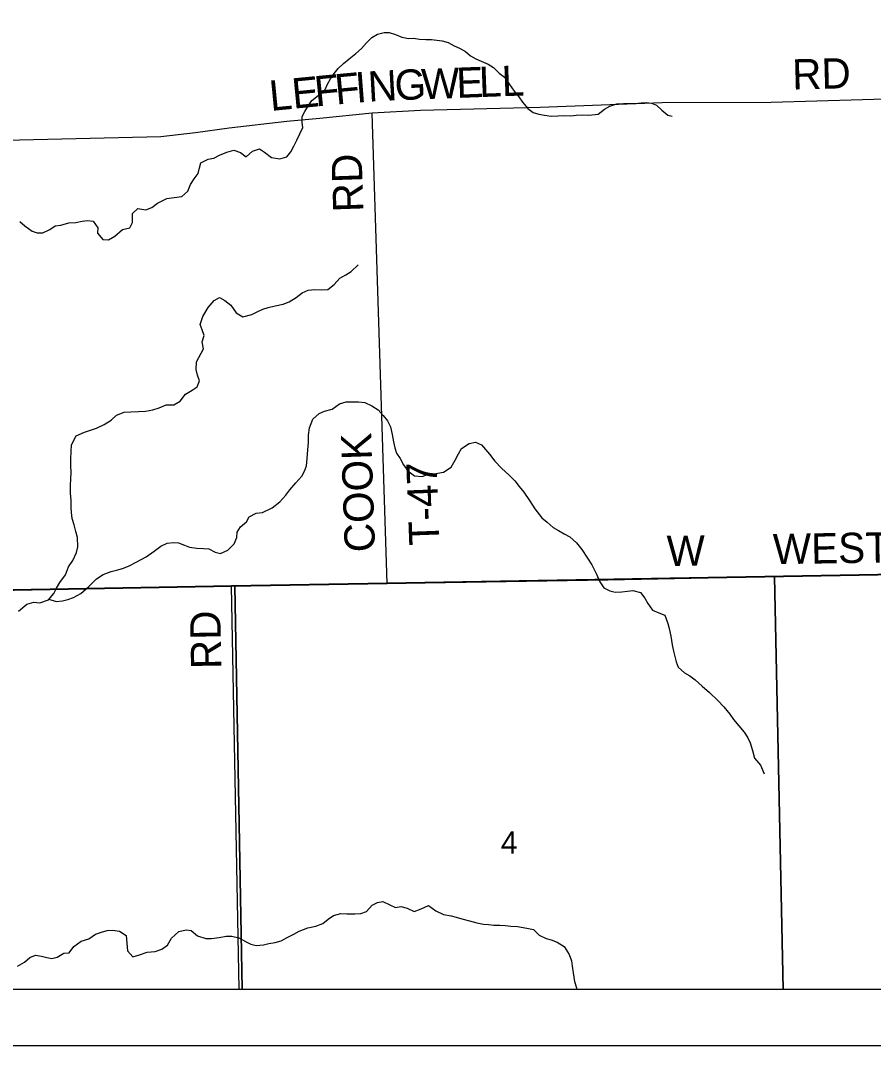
# Model space of a CAD drawing. Extents: x 0 to 34, y 0 to 22.
# Drawn here: x 4.883 to 6.483, y 9.902 to 11.824 of the extents above; entities that cross this region are included whole.
import ezdxf

# ---------------------------------------------------------------- set-up
doc = ezdxf.new("R2010")
doc.units = 0
for name, color, linetype in [('GM_X_Corporation', 7, 'Continuous'), ('GM_X_County_Road', 7, 'Continuous'), ('GM_X_County_Road_Text', 7, 'Continuous'), ('GM_X_Minor_River', 7, 'Continuous'), ('GM_X_Section_Text', 7, 'Continuous'), ('GM_X_Township_Road', 7, 'Continuous'), ('GM_X_Township_Road_Text', 7, 'Continuous'), ('SH_Data', 7, 'Continuous')]:
    doc.layers.add(name, color=color, linetype=linetype)

msp = doc.modelspace()

# ---------------------------------------------------------------- linework, layer by layer
at = {"layer": 'GM_X_Corporation'}
msp.add_lwpolyline([(6.7217, 15.9197), (5.5749, 15.8972), (5.1967, 15.8898), (4.4889, 15.8766), (2.7231, 15.8419), (2.7231, 10.7149), (3.2181, 10.7269), (4.6326, 10.7519), (5.2789, 10.7635), (5.571, 10.7686), (6.8097, 10.7901)], dxfattribs=at)
for points in [[(3.2288, 10.0075), (9.4322, 10.0075), (9.4266, 10.7304), (9.4256, 10.8527), (9.3392, 10.8506), (8.3328, 10.8251), (7.8767, 10.8135), (6.8339, 10.7907), (6.8097, 10.7901), (5.571, 10.7686), (5.2789, 10.7635), (4.6326, 10.7519), (3.2181, 10.7269)], [(6.3131, 10.0075), (7.3462, 10.0075), (7.3327, 10.8022), (6.8431, 10.7918), (6.4039, 10.7821), (6.297, 10.7801)], [(4.267, 10.0075), (5.299, 10.0075), (5.2854, 10.7626), (5.1477, 10.7602), (4.7405, 10.7544), (4.3079, 10.7484), (4.2548, 10.7474)], [(5.299, 10.0075), (6.3131, 10.0075), (6.297, 10.7801), (5.9849, 10.7744), (5.5658, 10.7674), (5.2854, 10.7626)]]:
    msp.add_lwpolyline(points, close=True, dxfattribs=at)
at = {"layer": 'GM_X_County_Road'}
msp.add_lwpolyline([(3.2183, 10.7263), (4.6328, 10.7513), (5.2791, 10.763), (5.5712, 10.7681), (6.8099, 10.7896)], dxfattribs=at)
at = {"layer": 'GM_X_Minor_River'}
for points in [[(5.4017, 11.5992), (5.4126, 11.6228), (5.4116, 11.6325), (5.4116, 11.6432), (5.4168, 11.6527), (5.4232, 11.6642), (5.4299, 11.6737), (5.4447, 11.6852), (5.4545, 11.6941), (5.4593, 11.704), (5.4649, 11.7143), (5.4713, 11.7239), (5.4788, 11.7334), (5.489, 11.743), (5.4996, 11.7518), (5.5121, 11.7618), (5.523, 11.771), (5.5321, 11.7818), (5.5419, 11.7917), (5.5528, 11.7979), (5.565, 11.801), (5.5745, 11.8007), (5.5863, 11.797), (5.5985, 11.7922), (5.6107, 11.79), (5.6202, 11.7905), (5.6313, 11.7887), (5.6434, 11.788), (5.6541, 11.7881), (5.6739, 11.7852), (5.6853, 11.7823), (5.6964, 11.7763), (5.7063, 11.7718), (5.7178, 11.7654), (5.7274, 11.7575), (5.7373, 11.7515), (5.7473, 11.7471), (5.7602, 11.7415), (5.7702, 11.7351), (5.7809, 11.7249), (5.7909, 11.7174), (5.8001, 11.7038), (5.809, 11.6913), (5.8175, 11.6804), (5.8248, 11.6705), (5.8344, 11.6584), (5.8447, 11.6509), (5.855, 11.648), (5.8657, 11.6458), (5.8786, 11.644), (5.8912, 11.6448), (5.9026, 11.6453), (5.9155, 11.645), (5.925, 11.6459), (5.9368, 11.6467), (5.949, 11.6461), (5.9665, 11.6477), (5.9785, 11.6573), (5.9884, 11.6627), (6.0013, 11.667), (6.0142, 11.6679), (6.0355, 11.6681), (6.0469, 11.6693), (6.0572, 11.6698), (6.0667, 11.6687), (6.0762, 11.665), (6.0862, 11.6556), (6.0973, 11.6458), (6.1053, 11.6443)], [(4.8916, 11.4386), (4.9051, 11.4286), (4.915, 11.4253), (4.9256, 11.4255), (4.9387, 11.4315), (4.9485, 11.4385), (4.959, 11.4395), (4.9741, 11.4439), (4.9874, 11.445), (4.9991, 11.4471), (5.0093, 11.4484), (5.0195, 11.4471), (5.0285, 11.4347), (5.0279, 11.4249), (5.0376, 11.4129), (5.0486, 11.4123), (5.0606, 11.419), (5.0748, 11.4318), (5.0883, 11.4348), (5.0935, 11.4447), (5.0932, 11.4614), (5.1032, 11.4711), (5.1184, 11.4688), (5.1297, 11.4728), (5.1405, 11.481), (5.1578, 11.49), (5.1718, 11.4914), (5.1862, 11.4932), (5.197, 11.5037), (5.202, 11.5163), (5.2091, 11.5264), (5.2164, 11.5368), (5.2189, 11.5471), (5.2218, 11.5566), (5.2356, 11.5633), (5.2458, 11.5651), (5.2567, 11.571), (5.2703, 11.5765), (5.2835, 11.5802), (5.2957, 11.5763), (5.3064, 11.5677), (5.3184, 11.5782), (5.3315, 11.583), (5.3411, 11.5764), (5.3538, 11.5664), (5.3698, 11.564), (5.383, 11.5677), (5.3904, 11.5773), (5.3959, 11.5881), (5.4017, 11.5992)], [(4.882, 11.4464), (4.8916, 11.4386)], [(5.0147, 11.0554), (5.026, 11.059), (5.0402, 11.0658), (5.0533, 11.0744), (5.0634, 11.0837), (5.0781, 11.0889), (5.0902, 11.0899), (5.1046, 11.0902), (5.1175, 11.0908), (5.1318, 11.0934), (5.1435, 11.097), (5.1566, 11.1026), (5.171, 11.1032), (5.1827, 11.1095), (5.193, 11.123), (5.205, 11.1305), (5.2147, 11.1367), (5.2191, 11.1478), (5.2155, 11.1584), (5.2126, 11.169), (5.2135, 11.1838), (5.2267, 11.208), (5.2242, 11.2212), (5.2277, 11.2331), (5.2241, 11.2433), (5.2202, 11.2535), (5.2252, 11.2687), (5.2355, 11.2853), (5.2466, 11.2988), (5.2567, 11.3039), (5.2667, 11.2988), (5.2775, 11.2899), (5.2876, 11.2753), (5.3006, 11.2679), (5.3172, 11.272), (5.327, 11.2775), (5.3379, 11.2823), (5.3477, 11.2855), (5.3612, 11.2888), (5.376, 11.2914), (5.3872, 11.2962), (5.4003, 11.3044), (5.4116, 11.313), (5.4225, 11.3178), (5.4353, 11.3191), (5.4478, 11.3186), (5.4599, 11.3192), (5.4715, 11.3282), (5.4819, 11.3406), (5.4935, 11.3465), (5.5033, 11.3527), (5.5163, 11.3651)], [(4.9367, 10.7383), (4.9505, 10.7339), (4.9622, 10.7357), (4.9724, 10.7378), (4.9826, 10.7414), (4.9968, 10.7493), (5.0114, 10.7625), (5.0259, 10.7764), (5.0382, 10.7846), (5.0537, 10.7906), (5.0657, 10.7935), (5.0763, 10.7964), (5.0872, 10.8011), (5.1018, 10.8086), (5.1191, 10.8181), (5.1341, 10.8283), (5.1468, 10.8376), (5.1584, 10.8435), (5.1701, 10.8449), (5.1796, 10.844), (5.1907, 10.8396), (5.2006, 10.836), (5.2143, 10.834), (5.2264, 10.8338), (5.2367, 10.8329), (5.2485, 10.8267), (5.2584, 10.8242), (5.2723, 10.8302), (5.2839, 10.8425), (5.2889, 10.8544), (5.2895, 10.8643), (5.2958, 10.8743), (5.307, 10.8833), (5.3121, 10.8932), (5.3252, 10.8999), (5.337, 10.9013), (5.3554, 10.9096), (5.3699, 10.9209), (5.3811, 10.9333), (5.3885, 10.9437), (5.3996, 10.9568), (5.4107, 10.9692), (5.4162, 10.9788), (5.4198, 10.9888), (5.4211, 11.0025), (5.4219, 11.0188), (5.4236, 11.0325), (5.4237, 11.0458), (5.425, 11.0599), (5.4315, 11.076), (5.4434, 11.0864), (5.4536, 11.0908), (5.4679, 11.0949), (5.4813, 11.105), (5.4942, 11.1083), (5.5074, 11.1082), (5.5173, 11.1084), (5.529, 11.1075), (5.542, 11.1009), (5.5539, 11.0935), (5.5632, 11.0827), (5.5714, 11.073), (5.5773, 11.0617), (5.5806, 11.0473), (5.5831, 11.0337), (5.5856, 11.0223), (5.5884, 11.0121), (5.595, 11.0024), (5.6013, 10.9907), (5.6095, 10.9791), (5.6221, 10.9698), (5.6366, 10.9686), (5.6486, 10.973), (5.6592, 10.9736), (5.6766, 10.9766), (5.6908, 10.986), (5.6985, 10.9994), (5.7044, 11.0113), (5.7102, 11.0209), (5.7245, 11.0303), (5.7365, 11.0332), (5.748, 11.0277), (5.7627, 11.0105), (5.7728, 10.9974), (5.7852, 10.9844), (5.7995, 10.971), (5.8106, 10.9602), (5.8184, 10.95), (5.8269, 10.9392), (5.8378, 10.9238), (5.8476, 10.9081), (5.8608, 10.8912), (5.8708, 10.883), (5.8824, 10.873), (5.8923, 10.8671), (5.903, 10.8613), (5.9134, 10.8554), (5.9261, 10.8442), (5.9358, 10.8319), (5.9463, 10.8154), (5.9545, 10.8026)], [(4.8796, 10.7162), (4.8953, 10.7291), (4.9085, 10.7327), (4.9199, 10.7318), (4.9357, 10.7371), (4.9457, 10.749), (4.9512, 10.7594), (4.9574, 10.7698), (4.9678, 10.7844), (4.9732, 10.7989), (4.9817, 10.8109), (4.9882, 10.8258), (4.991, 10.8369), (4.9903, 10.854), (4.9875, 10.8653), (4.9838, 10.8778), (4.9802, 10.8899), (4.9792, 10.9009), (4.9787, 10.9103), (4.9784, 10.9236), (4.9771, 10.9373), (4.9772, 10.9521), (4.9781, 10.9635), (4.9786, 10.9768), (4.978, 10.9886), (4.9781, 11.0019), (4.9783, 11.0156), (4.9792, 11.0281), (4.9876, 11.045), (5.0034, 11.0514), (5.0147, 11.0554)], [(5.9545, 10.8026), (5.9632, 10.7853), (5.9699, 10.771), (5.9769, 10.7597), (5.9884, 10.7539), (5.9987, 10.7514), (6.0111, 10.752), (6.0213, 10.7537), (6.0316, 10.7547), (6.046, 10.7508), (6.0538, 10.7403), (6.0597, 10.7301), (6.0686, 10.7178), (6.0801, 10.7131), (6.0915, 10.7087), (6.0971, 10.6932), (6.0996, 10.6834), (6.1025, 10.669), (6.1054, 10.6531), (6.1075, 10.641), (6.1104, 10.6312), (6.1128, 10.621), (6.1164, 10.6108), (6.1284, 10.6004), (6.1387, 10.5945), (6.1487, 10.5875), (6.1614, 10.5756), (6.1753, 10.5633), (6.1907, 10.5488), (6.2019, 10.5368), (6.2135, 10.523), (6.2202, 10.5132), (6.2403, 10.4889), (6.2473, 10.4788), (6.2513, 10.469), (6.2557, 10.4547), (6.2598, 10.4407), (6.2706, 10.4272), (6.2778, 10.411)], [(5.1938, 10.1183), (5.2033, 10.117), (5.2156, 10.107), (5.2312, 10.1023), (5.2418, 10.1025), (5.2558, 10.1043), (5.2691, 10.1065), (5.2797, 10.1067), (5.2926, 10.1035), (5.3052, 10.0969), (5.3152, 10.0918), (5.3251, 10.0893), (5.3391, 10.0904), (5.3489, 10.0928), (5.361, 10.0946), (5.3723, 10.0982), (5.3835, 10.1041), (5.3959, 10.1101), (5.4057, 10.1163), (5.4222, 10.122), (5.4369, 10.1253), (5.4505, 10.1301), (5.4606, 10.1383), (5.4703, 10.1457), (5.4842, 10.1494), (5.4953, 10.1484), (5.51, 10.1483), (5.5218, 10.1489), (5.5323, 10.1526), (5.5427, 10.1645), (5.5528, 10.1697), (5.563, 10.1714), (5.576, 10.1652), (5.5867, 10.1604), (5.5965, 10.1622), (5.6083, 10.1593), (5.6217, 10.1531), (5.6349, 10.158), (5.6484, 10.1643), (5.6619, 10.1543), (5.6764, 10.147), (5.6908, 10.1446), (5.7004, 10.1425), (5.711, 10.1389), (5.7251, 10.1357), (5.7392, 10.1318), (5.7514, 10.1294), (5.7609, 10.1285), (5.7707, 10.1275), (5.7821, 10.127), (5.7931, 10.1264), (5.803, 10.1255), (5.8155, 10.1246), (5.833, 10.1219), (5.8452, 10.119), (5.856, 10.1086), (5.8689, 10.1024), (5.8785, 10.0999), (5.8895, 10.0952), (5.9026, 10.0875), (5.9119, 10.0721), (5.9163, 10.0604), (5.918, 10.0502), (5.9194, 10.038), (5.922, 10.0217), (5.9256, 10.0097), (5.9265, 10.0075)], [(4.8779, 10.0503), (4.8907, 10.0578), (4.9007, 10.0667), (4.9116, 10.0711), (4.9227, 10.0694), (4.9326, 10.0666), (4.9424, 10.0645), (4.9523, 10.067), (4.9646, 10.0748), (4.9744, 10.0757), (4.9837, 10.0873), (4.9972, 10.0971), (5.0115, 10.1019), (5.0242, 10.1101), (5.0355, 10.1141), (5.0461, 10.117), (5.0559, 10.1176), (5.0692, 10.1163), (5.0815, 10.1078), (5.0825, 10.0934), (5.0843, 10.0794), (5.094, 10.0678), (5.1068, 10.0715), (5.1211, 10.0767), (5.1358, 10.0777), (5.1486, 10.0821), (5.1591, 10.0896), (5.1664, 10.103), (5.1802, 10.1154), (5.1938, 10.1183)]]:
    msp.add_lwpolyline(points, dxfattribs=at)
at = {"layer": 'GM_X_Township_Road'}
for p, q in [((5.5712, 10.7681), (5.5427, 11.6499)), ((5.2934, 10.0075), (5.2791, 10.763))]:
    msp.add_line(p, q, dxfattribs=at)
msp.add_lwpolyline([(6.8095, 11.6826), (6.5476, 11.6773), (6.2911, 11.6698), (6.0863, 11.6692), (5.8575, 11.6606), (5.6333, 11.6546), (5.5427, 11.6499), (5.4445, 11.6399), (5.3828, 11.6341), (5.2747, 11.6214), (5.2115, 11.6126), (5.1468, 11.6056), (4.6159, 11.5926)], dxfattribs=at)
at = {"layer": 'SH_Data'}
msp.add_line((2.6297, 9.9017), (9.6297, 9.9017), dxfattribs=at)

# ---------------------------------------------------------------- texts
at = {"layer": 'GM_X_County_Road_Text'}
for s, height, rotation, p in [('WESTERN', 0.05682, 0.8747, (6.2945, 10.804)), ('W', 0.0568, 0.7248, (6.0954, 10.8006))]:
    msp.add_text(s, height=height, rotation=rotation, dxfattribs=at).set_placement(p)
at = {"layer": 'GM_X_Section_Text'}
msp.add_text('4', height=0.0419, rotation=0, dxfattribs=at).set_placement((5.784, 10.2611))
at = {"layer": 'GM_X_Township_Road_Text'}
for s, height, rotation, p in [('RD', 0.05682, 1.4826, (6.331, 11.6939)), ('F', 0.0568, 5.3768, (5.4754, 11.6658)), ('I', 0.0568, 4.4071, (5.5133, 11.6694)), ('N', 0.0568, 3.1198, (5.5362, 11.6712)), ('G', 0.0568, 2.1533, (5.5859, 11.6739)), ('W', 0.0568, 2.1364, (5.6359, 11.6758)), ('E', 0.0568, 2.1392, (5.7016, 11.6782)), ('L', 0.0568, 2.1347, (5.7441, 11.6798)), ('L', 0.0568, 2.1392, (5.7866, 11.6814)), ('L', 0.0568, 5.5844, (5.3527, 11.6538)), ('E', 0.0568, 5.586, (5.395, 11.658)), ('F', 0.0568, 5.5825, (5.4373, 11.6621)), ('RD', 0.05682, 91.9758, (5.5267, 11.465)), ('COOK', 0.05682, 91.9414, (5.5484, 10.8275)), ('T-47', 0.05682, 92.1213, (5.6692, 10.8402)), ('RD', 0.05682, 90.9872, (5.26, 10.6079))]:
    msp.add_text(s, height=height, rotation=rotation, dxfattribs=at).set_placement(p)

doc.saveas('drawing.dxf')
